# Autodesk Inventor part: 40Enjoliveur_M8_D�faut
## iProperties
Created: 2011-01
Part Number: 40Enjoliveur_M8_D�faut
Document SubType Name: Modeling
Designer: eric
Density: 1 g/cm^3
Mass: 1.78368 g
Surface Area: 14.472 cm^2
Volume: 1.78368 cm^3
Author: eric
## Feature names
1. Base1
